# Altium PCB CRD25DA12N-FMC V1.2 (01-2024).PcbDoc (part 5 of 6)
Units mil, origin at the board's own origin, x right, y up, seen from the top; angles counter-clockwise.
Board outline 8000 x 8000 mil, 6 copper layers (Top Layer, Layer 2, Layer 3, Layer 4, Layer 5, Bottom Layer), stack 91 mil thick; 574 components, 325 nets, 1631 pads, 633 vias.
Unrouted connection lines stored in the file: 1.
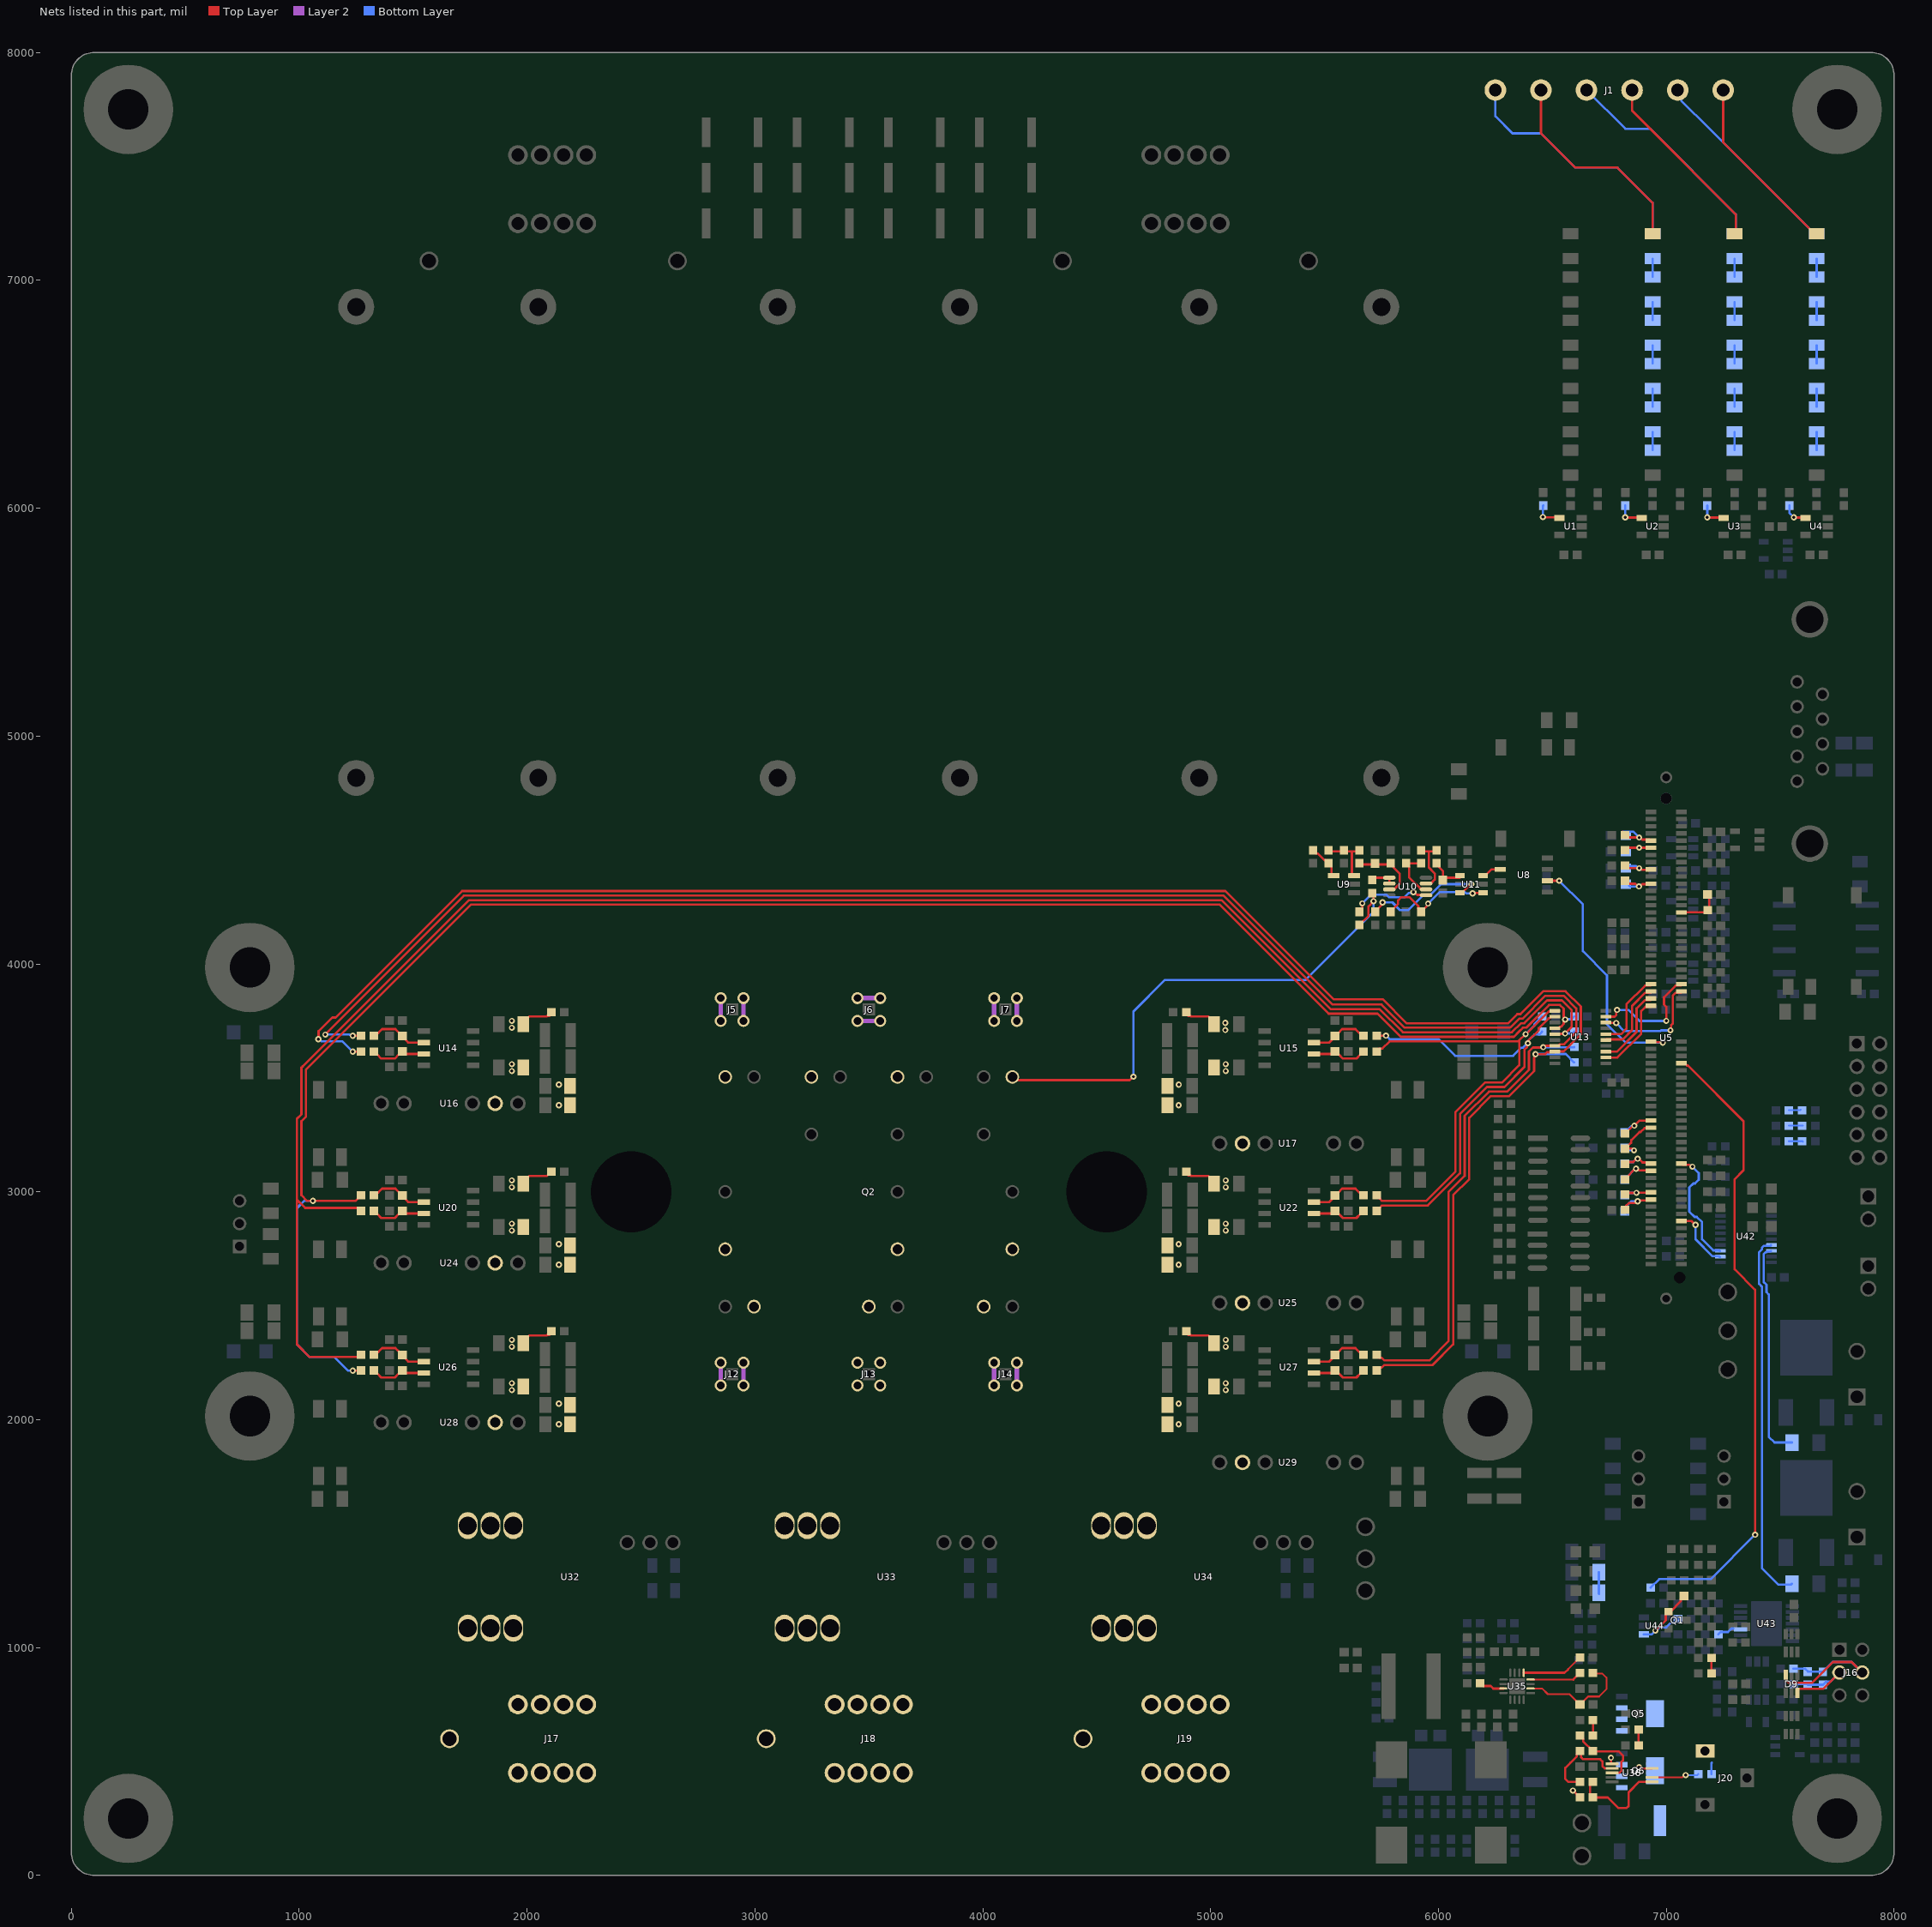
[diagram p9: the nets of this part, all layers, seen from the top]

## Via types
v1: diameter 27, hole 13, Top Layer to Bottom Layer, tented both sides, 537 vias
v2: diameter 50, hole 28, Top Layer to Bottom Layer, tented both sides, 76 vias
v3: diameter 19.68, hole 7.87, Top Layer to Bottom Layer, tented top, 15 vias
v4: diameter 19.68, hole 7.87, Top Layer to Bottom Layer, tented both sides, 5 vias

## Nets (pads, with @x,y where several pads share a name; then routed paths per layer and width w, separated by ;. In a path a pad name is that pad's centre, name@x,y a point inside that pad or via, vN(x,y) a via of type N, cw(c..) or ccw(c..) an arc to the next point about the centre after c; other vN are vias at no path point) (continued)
NetR137_2: R137.2 U35.5 | length 274.5
  Top Layer w8: 6569.74,905.26 6620.47,956 R137.2@6621.38,956
  Top Layer w10: U35.5@6374.53,889.23 6553.71,889.23 6569.74,905.26
NetR138_1: R138.1 R140.2 | length 68
  Top Layer w10: R140.2@7198.62,886 R138.1@7198.62,954
NetR139_1: R139.1 U35.4 | length 228.9
  Top Layer w8: U35.4@6404.23,859.53 6592,859.53
  Top Layer w10: 6592,859.53 6620.47,888 R139.1@6621.38,888
NetR141_2: R141.2 U35.11 | length 112.3
  Top Layer w10: R141.2@6183.62,844 6196.58,831.04 6229.48,831.04 6240.69,819.84 6264.04,819.84 6285.48,819.87 U35.11@6285.77,820.16
NetR142_2: R142.2 R144.1 | length 72.5
  Top Layer w10: R142.2@6675,685 6678.62,681.38 R144.1@6678.62,614
NetR143_2: R143.2 R145.1 | length 70
  Top Layer w10: R145.1@6878.62,570 R143.2@6878.62,640
NetR144_2: R144.2 R146.1 U36.3 | length 348.4
  Top Layer w8: U36.3@6761.17,449.69 6795,449.69
  Top Layer w10: R144.2@6621.38,614 6622.28,614 6635.24,601.04 6635.24,588.48 6677.72,546 R146.1@6678.62,546 6679.94,544.68 6769.2,544.68 6770.38,543.5 6791.81,543.5 6810,525.31 6810,505 6803.1,498.1 6803.1,458.1 6795,450 6795,449.69
NetR146_2: R146.2 R147.1 U36.2 | length 418.9
  Top Layer w8: 6730,469.69 U36.2@6762.91,469.69
  Top Layer w10: R147.1@6621.38,410 6570,410 6556.5,423.5 6556.5,471.5 6580,495 6607.52,522.52 6607.52,533.04 R146.2@6620.47,546 ; R146.2@6621.38,546 R146.2@6620.47,546 ; 6730,469.69 6720,479.69 6720,500 6710,510 6635,510 6626.1,518.9 6626.1,536.38 6626.1,540.38 R146.2@6620.47,546
NetR147_2: R147.2 R148.1 U36.6 | length 442.1
  Top Layer w10: R148.1@6678.62,342 6743,342 6790,295 6825.31,295 6835,304.69 6835,365 6880.63,410.63 U36.6@6937.09,410.63 ; R147.2@6678.62,410 6677.96,410 6665,397.04 6665,354.96 6677.96,342 R148.1@6679.53,342
NetR149_2: R149.2 R153.1 | length 79.8
  Bottom Layer w10: R153.1@7660,7015.12 R149.2@7660,7094.88
NetR150_2: R150.2 R154.1 | length 79.8
  Bottom Layer w10: R154.1@7300,7015.12 R150.2@7300,7094.88
NetR151_2: R151.2 R155.1 | length 79.8
  Bottom Layer w10: R155.1@6940,7015.12 R151.2@6940,7094.88
NetR153_2: R153.2 R157.1 | length 79.8
  Bottom Layer w10: R157.1@7660,6825.12 R153.2@7660,6904.88
NetR154_2: R154.2 R158.1 | length 79.8
  Bottom Layer w10: R158.1@7300,6825.12 R154.2@7300,6904.88
NetR155_2: R155.2 R159.1 | length 79.8
  Bottom Layer w10: R159.1@6940,6825.12 R155.2@6940,6904.88
NetR157_2: R157.2 R161.1 | length 79.8
  Bottom Layer w10: R161.1@7660,6635.12 R157.2@7660,6714.88
NetR158_2: R158.2 R162.1 | length 79.8
  Bottom Layer w10: R162.1@7300,6635.12 R158.2@7300,6714.88
NetR159_2: R159.2 R163.1 | length 79.8
  Bottom Layer w10: R163.1@6940,6635.12 R159.2@6940,6714.88
NetR161_2: R161.2 R165.1 | length 79.8
  Bottom Layer w10: R165.1@7660,6445.12 R161.2@7660,6524.88
NetR162_2: R162.2 R166.1 | length 79.8
  Bottom Layer w10: R166.1@7300,6445.12 R162.2@7300,6524.88
NetR163_2: R163.2 R167.1 | length 79.8
  Bottom Layer w10: R167.1@6940,6445.12 R163.2@6940,6524.88
NetR165_2: R165.2 R169.1 | length 79.8
  Bottom Layer w10: R169.1@7660,6255.12 R165.2@7660,6334.88
NetR166_2: R166.2 R170.1 | length 79.8
  Bottom Layer w10: R170.1@7300,6255.12 R166.2@7300,6334.88
NetR167_2: R167.2 R171.1 | length 79.8
  Bottom Layer w10: R171.1@6940,6255.12 R167.2@6940,6334.88
NetR174_2: R174.2 U4.4 | length 112.5
  Top Layer w10: v1(7560,5960) 7561.3,5958.7 7610.47,5958.7 U4.4@7611.77,5957.4
  Bottom Layer w10: R174.2@7540,6011.38 7540,5980 v1(7560,5960)
NetR176_2: R176.2 U3.4 | length 124.2
  Top Layer w10: v1(7180,5960) 7181.3,5958.7 7250.47,5958.7 U3.4@7251.77,5957.4
  Bottom Layer w10: v1(7180,5960) R176.2@7180,6011.38
NetR178_2: R178.2 U2.4 | length 124.2
  Top Layer w10: v1(6820,5960) 6821.3,5958.7 6890.47,5958.7 U2.4@6891.77,5957.4
  Bottom Layer w10: v1(6820,5960) R178.2@6820,6011.38
NetR180_2: R180.2 U1.4 | length 125.4
  Top Layer w10: v1(6458.58,5961.42) 6460.59,5959.41 6529.76,5959.41 U1.4@6531.77,5957.4
  Bottom Layer w10: v1(6458.58,5961.42) 6458.58,6009.96 R180.2@6460,6011.38
NetR204_2: R204.2 R205.1 | length 52.2
  Bottom Layer w8: R205.1@7538.62,3358 7588,3358 R204.2@7590,3360
NetR206_2: R206.2 R207.1 | length 61.4
  Bottom Layer w8: R207.1@7538.62,3290 R206.2@7596.38,3290 R206.2@7600,3290
NetR208_2: R208.2 R209.1 | length 62.2
  Bottom Layer w8: R209.1@7538.62,3222 R208.2@7596.38,3222 7598,3222 R208.2@7600,3220
NetR216_1: R216.1 R219.2 | length 95.4
  Bottom Layer w10: R216.1@6704.1,1330 R219.2@6704.1,1240 6704.1,1235.9 R219.2@6705,1235
NetR228_1: R228.1 U43.3 | length 76.6
  Bottom Layer w10: R228.1@7228.62,1058 7238.6,1067.98 7271.26,1067.98 7286.55,1083.27 7294.76,1083.27
NetR246_1: R246.1 U36.7 | length 210.4
  Top Layer w8: U36.7@6937.09,430.32 7070.17,430.32 7079.86,440 v1(7085,440)
  Bottom Layer w8: v1(7085,440) 7136.38,440 R246.1@7141.38,445
NTC1: Q2.NTC2 R56.1 R59.2 | length 2278.5
  Top Layer w10: Q2.NTC2@4129.92,3503.94 4143.45,3503.94 4157.39,3490 4645.4,3490 4660.4,3505 v1(4661.5,3505) ; R59.2@5654,4171.38 5654,4172.28 5693.04,4211.33 5693.04,4253.04 v1(5715,4275) 5715,4306.38 R56.1@5710,4311.38
  Bottom Layer w10: v1(4661.5,3505) 4661.5,3791.5 4800,3930 5416.72,3930 5715,4228.28 v1(5715,4275)
NTC1_BUF: R59.1 U10.5 | length 359
  Top Layer w10: R59.1@5654,4228.62 ccw(c5654,4240.37) 5665.75,4240.37 v1(5665.75,4265.68) ; v1(5890.31,4315.31) 5894.3,4315.31 5906.51,4303.09 5944.23,4303.09 U10.5@5945.71,4301.61
  Bottom Layer w10: v1(5665.75,4265.68) 5665.75,4266.05 5703.19,4303.5 5772.11,4303.5 5782.79,4292.81 5851.71,4292.81 5870.94,4312.05 5887.05,4312.05 v1(5890.31,4315.31)
NTC1_FB: R53.2 R54.2 U10.7 | length 246.9
  Top Layer w10: R53.2@5925,4493.62 5958.5,4493.62 ; U10.7@5945.71,4352.8 5966.5,4352.8 5972.23,4358.53 5972.64,4358.53 5984.27,4370.16 5984.27,4396.74 5958.5,4422.51 5958.5,4493.62 ; R54.2@5992,4493.62 5958.5,4493.62
NTC1_INV: R52.2 R53.1 U10.6 | length 229.9
  Top Layer w10: R53.1@5925,4441.38 R52.2@5858,4441.38 5870.96,4428.42 5870.96,4380.76 5918.78,4332.94 5919.19,4332.94 5924.92,4327.2 U10.6@5945.71,4327.2
NTC_B0: R47.2 R48.1 R49.2 U9.3 | length 251.4
  Top Layer w10: R47.2@5515,4493.62 5586,4493.62 5620,4493.62 ; U9.3@5630.08,4387.4 5626.61,4387.4 5620,4394.02 5620,4437.94 5620,4493.62 ; R49.2@5654,4493.62 5620,4493.62
NTC_B1: R46.2 R47.1 U9.4 | length 155.8
  Top Layer w10: R46.2@5450,4498.62 5450,4497.72 5462.96,4484.76 5470.52,4484.76 5500.04,4455.24 5505.04,4455.24 5518,4442.28 R47.1@5518,4441.38 5518,4437.28 5530.96,4424.33 5530.96,4396.37 U9.4@5539.92,4387.4
NTC_BIAS: C14.1 R49.1 R51.2 U10.3 | length 295.5
  Top Layer w10: R49.1@5654,4436.38 5721.96,4436.38 5722,4436.42 5794.05,4436.42 5802.96,4427.52 5802.96,4423.42 5830,4396.38 5830,4351.72 5811.22,4332.94 5810.81,4332.94 5805.08,4327.2 U10.3@5784.29,4327.2
NTC_BIAS_BUF: R56.2 U10.1 U10.2 | length 103.9
  Top Layer w10: R56.2@5710,4368.62 5719.76,4378.39 U10.1@5784.29,4378.39 U10.2@5784.29,4352.8
NTC_DIV: R61.2 R62.1 U11.4 | length 523.1
  Top Layer w10: R61.2@5790,4228.62 5790,4229.53 5823.08,4262.6 5823.08,4278.38 5837.51,4292.81 5851.71,4292.81 5852,4293.11 5872.2,4293.11 5912.04,4253.26 5912.04,4241.58 R62.1@5925,4228.62 ; R62.1@5925,4225 R62.1@5925,4228.62 ; v1(5955,4265) 5951.75,4261.75 5951.75,4256.27 5925,4229.53 R62.1@5925,4228.62 ; v1(6150.15,4309.85) 6151.53,4311.22 6193.62,4311.22 U11.4@6196.2,4313.8
  Bottom Layer w10: v1(5955,4265) 6005,4315 6116.65,4315 6121.65,4310 6150,4310 v1(6150.15,4309.85)
NTC_ISO: U5.57 U8.6 | length 1100.5
  Top Layer w10: U8.6@6478.35,4365 v1(6530,4365) ; U5.57@6933.07,3659.25 6935.2,3657.13 6982.87,3657.13 v1(6985,3655)
  Bottom Layer w10: v1(6530,4365) 6634.13,4260.87 6634.13,4055.87 6740,3950 6740,3735 6820,3655 v1(6985,3655)
NTC_MOD: C18.1 R54.1 U11.1 | length 142.2
  Top Layer w10: R54.1@5992,4436.38 5992,4435.47 6020,4407.47 6020,4380.52 6023.12,4377.4 6024.22,4378.5 U11.1@6093.01,4378.5
NTC_PWM: U8.2 U11.6 | length 90.3
  Top Layer w10: U11.6@6196.18,4387.4 6206.02,4387.4 6233.62,4415 U8.2@6271.65,4415 U8.2@6275,4415
NTC_SET: R60.2 U11.3 | length 565.9
  Top Layer w10: R60.2@5722,4228.62 5722,4229.53 v1@5751.75,4259.27 ; U11.3@6093.82,4312.6 6103.66,4312.6 6141.06,4350 v1(6145,4350) v1@6150,4350
  Bottom Layer w10: v1(5755,4270) 5798.05,4270 5831.94,4236.11 5867.58,4236.11 5931.12,4299.64 5961.36,4299.64 6011.72,4350 v1(6145,4350)
RELAY1: R217.1 U42.17 | length 1624.2
  Bottom Layer w10: U42.17@7459.41,2765.59 7456.69,2762.87 7428.03,2762.87 7420,2754.84 7420,2747.41 7407.58,2734.99 7407.58,2596.32 7420,2583.91 7420,1348.28 7492.43,1275.86 7547.65,1275.86 R217.1@7551.79,1280
RELAY1_OUT: U5.92 U42.3 | length 532.2
  Top Layer w10: U5.92@7066.93,3123.82 7071.77,3118.98 7101.42,3118.98 7110.4,3110 v1(7115,3110)
  Bottom Layer w10: v1(7115,3110) 7142.55,3082.45 7142.55,3052.99 7126.32,3036.75 7119.15,3036.75 7101.5,3019.11 7101.5,2913.19 7124.77,2889.92 7133.73,2889.92 7157,2866.65 7157,2792.03 7206.16,2742.87 7232.13,2742.87 U42.3@7235,2740
RELAY2: R214.1 U42.18 | length 960.6
  Bottom Layer w10: U42.18@7459.41,2740 7457.56,2738.15 7443.58,2738.15 7439.74,2734.31 7435.18,2734.31 7427.58,2726.71 7427.58,2604.61 7440,2592.19 7440,2560 7450,2550 7450,1925 7475,1900 7551.56,1900 R214.1@7551.79,1899.76
RELAY2_OUT: U5.108 U42.2 | length 268.3
  Top Layer w10: U5.108@7066.93,2871.85 7109.87,2871.85 v1@7126.87,2854.85
  Bottom Layer w10: v1(7128.5,2854.85) 7128.5,2792.25 7203.47,2717.28 7232.13,2717.28 U42.2@7235,2714.41
RSLV_PWM: R218.1 U5.64 | length 2800.8
  Top Layer w10: U5.64@7066.93,3564.76 7080.71,3564.76 7091.36,3554.11 7095.11,3554.11 7101.55,3547.67 7338.86,3310.36 7338.86,3093.86 7300,3055 7300,2660 7390,2570 v1(7390,1495)
  Bottom Layer w10: R218.1@6931.38,1263 6932.28,1263 6969.17,1299.89 7194.89,1299.89 v1(7390,1495)
RSLV_PWM_FILT: C95.1 Q1.1 R224.2 U44.1 | length 383.9
  Top Layer w10: v1(6952.26,1074.16) 6997.91,1119.81 6997.91,1146.65 7008.66,1157.4 Q1.1@7010.63,1157.4 ; Q1.1@7015.63,1157.4 7017.6,1157.4 7063.76,1203.57 7063.76,1213.14 7077.63,1227 C95.1@7078.58,1227
  Bottom Layer w10: U44.1@6901.77,1057.6 6935.7,1057.6 v1(6952.26,1074.16) 6956.86,1074.16 6970.8,1088.1 7000.44,1088.1 7019.3,1106.96 7031.43,1106.96 7050.47,1126 R224.2@7051.38,1126
S1: C52.1 C62.2 C67.1 C71.2 J5.2 J5.3 J5.4 J5.5 Q2.S1 R88.1 U24.6 | length 346.1
  Top Layer w10: C52.1@1984.19,3035 1984.19,3043.91 2010.28,3070 2087.47,3070 2097.47,3080 R88.1@2106.38,3080
  Layer 2 w20: J5.4@2850,3750 J5.2@2850,3850 ; J5.5@2950,3750 J5.3@2950,3850
  other v1: 2140,2680 2140,2770 1933.37,2830 1933.37,2860 1933.37,3020 1933.37,3050
S2: C77.1 C83.2 C87.1 C89.2 J12.2 J12.3 J12.4 J12.5 Q2.S2 R112.1 U28.6 | length 346.1
  Top Layer w10: C77.1@1984.19,2335 1984.19,2343.91 2010.28,2370 2086.66,2370 2088.7,2372.04 2098.42,2372.04 R112.1@2106.38,2380
  Layer 2 w20: J12.4@2850,2150 J12.2@2850,2250 ; J12.5@2950,2150 J12.3@2950,2250
  other v1: 2140,1980 2140,2070 1933.37,2130 1933.37,2160 1933.37,2320 1933.37,2350
S3: C30.1 C36.2 C40.1 C42.2 J6.2 J6.3 J6.4 J6.5 Q2.S3 R67.1 U16.6 | length 346.1
  Top Layer w10: C30.1@1984.19,3735 1984.19,3743.91 2010.28,3770 2086.66,3770 2088.7,3772.04 2098.42,3772.04 R67.1@2106.38,3780
  Layer 2 w20: J6.4@3450,3750 J6.5@3550,3750 ; J6.2@3450,3850 J6.3@3550,3850
  other v1: 2140,3380 2140,3470 1933.37,3530 1933.37,3560 1933.37,3720 1933.37,3750
S4: C78.2 C84.1 C88.1 C90.2 J13.2 J13.3 J13.4 J13.5 Q2.S4 R113.1 U29.6 | length 146.1
  Top Layer w10: R113.1@4893.62,2380 4901.58,2372.04 4911.3,2372.04 4913.34,2370 4989.72,2370 5015.81,2343.91 C78.2@5015.81,2335
  other v1: 4860,1980 4860,2070 5066.63,2130 5066.63,2160 5066.63,2320 5066.63,2350
S5: C31.2 C37.1 C41.1 C43.2 J7.2 J7.3 J7.4 J7.5 Q2.S5 R68.1 U17.6 | length 346.1
  Top Layer w10: R68.1@4893.62,3780 4901.58,3772.04 4911.3,3772.04 4913.34,3770 4989.72,3770 5015.81,3743.91 C31.2@5015.81,3735
  Layer 2 w20: J7.4@4050,3750 J7.2@4050,3850 ; J7.5@4150,3750 J7.3@4150,3850
  other v1: 4860,3380 4860.39,3469.95 5066.63,3530 5066.63,3560 5065,3710 5065,3741.5
S6: C53.2 C63.1 C68.1 C72.2 J14.2 J14.3 J14.4 J14.5 Q2.S6 R89.1 U25.6 | length 346.1
  Top Layer w10: R89.1@4893.62,3080 4901.58,3072.04 4911.3,3072.04 4913.34,3070 4989.72,3070 5015.81,3043.91 C53.2@5015.81,3035
  Layer 2 w20: J14.4@4050,2150 J14.2@4050,2250 ; J14.5@4150,2150 J14.3@4150,2250
  other v1: 4860,2680 4860,2770 5066.63,2830 5066.63,2860 5066.63,3020 5066.63,3050
SIN: C19.1 R58.2 U5.30 | length 184.6
  Top Layer w10: U5.30@7066.93,4226.18 7171.56,4226.18 R58.2@7181.38,4236 ; R58.2@7187.44,4240 7188.72,4241.28 7188.72,4303.72 C19.1@7190,4305
SIN_N: C177.2 D9.6 J16.4 R235.1 R236.1 | length 767.9
  Top Layer w10: D9.6@7524.41,879.37 7528.27,875.51 7528.27,854.05 7536.59,845.73 7640.73,845.73 7731.5,936.5 7813.5,936.5 J16.4@7860,890
  Bottom Layer w10: R235.1@7558.62,907 7609.53,907 C177.2@7622,894.53 ; C177.2@7622,893.58 7689.96,893.58 R236.1@7689.96,896.48 ; R236.1@7688,893.62 7688,894.53 R236.1@7689.96,896.48 ; J16.4@7860,890 7813.5,936.5 7729.97,936.5 R236.1@7689.96,896.48
SIN_P: C177.1 D9.3 J16.3 R236.2 R238.1 | length 454.7
  Top Layer w10: D9.3@7575.59,800.63 7575.59,814.41 7579.45,818.27 7688.27,818.27 J16.3@7760,890
  Bottom Layer w10: R238.1@7558.62,839 7619.42,839 7622,836.42 R236.2@7688,836.38 7688,837.28 7700.96,850.24 7720.24,850.24 J16.3@7760,890
U: Q2.U U32.4 U32.5 U32.6
U_HI_OC: C145.1 R84.2 U5.79 | length 191.4
  Top Layer w10: R84.2@6818.62,3256 6819.53,3256 6850.27,3286.75 6856.75,3286.75 6882.8,3312.8 U5.79@6933.07,3312.8
  Bottom Layer w10: C145.1@6818.58,3261 6819.53,3261 6845.27,3286.75 6856.75,3286.75 v1(6860,3290)
U_HS: R94.1 R121.1 R197.2 U13.14 | length 8144.5
  Top Layer w10: v1(1235,2215) 1270.38,2215 R121.1@1271.38,2216 ; R94.1@1271.38,2984 1270.47,2984 1257.52,2971.04 1257.52,2970.14 1247.38,2960 v1(1060,2960) 1035,2960 1010,2985 1010,3310 1030,3330 1030,3536.41 1753.59,4260 5040.15,4260 5518.28,3781.86 5733.28,3781.86 5835.15,3680 6331.11,3680 6355.11,3704 6371.11,3720 6385.17,3720 6485.17,3820 6533.43,3820 6550,3803.43 v1@6550,3755 ; U13.14@6510.59,3717.36 6526.34,3717.36 6533.06,3724.08 6537.62,3724.08 6550,3736.46 v1@6550,3755 ; v1(6556.77,3755.76) 6550.76,3755.76 v1@6550,3755
  Bottom Layer w10: v1(1060,2960) 1021.65,2960 990,2928.35 990,2330 1045,2275 1155,2275 1215,2215 v1(1235,2215) ; v1(6556.77,3755.76) 6558.05,3757.04 6583.42,3757.04 R197.2@6596.38,3770
U_HS+_FILT: C56.1 R94.2 U20.2 | length 256.7
  Top Layer w10: R94.2@1328.62,2984 1341.58,2996.96 1346.96,2996.96 1363.86,3013.86 1422.76,3013.86 1438.76,2997.86 1449.53,2987.1 1449.53,2984 1478.53,2955 U20.2@1546.73,2955
U_HS-_FILT: C81.1 R121.2 U26.3 | length 258
  Top Layer w10: R121.2@1328.62,2216 1329.53,2216 1342.48,2203.04 1342.48,2202.52 1360,2185 1420,2185 1437.14,2202.14 1447.14,2202.14 1453.58,2208.58 C81.1@1453.58,2216 ; C81.1@1448.58,2216 1454.79,2209.79 1459.58,2205 U26.3@1546.73,2205
U_HS_PWM: U5.49 U13.6 | length 353.2
  Top Layer w10: U13.6@6735,3691.77 6801.77,3691.77 6825,3715 6825,3822.63 6906.98,3904.61 6930.16,3904.61 U5.49@6935,3909.45
U_LO_OC: C146.1 R85.2 U5.81 | length 250
  Top Layer w10: v1@6855,3189.96 6858.45,3186.51 v1(6858.45,3181.91) ; v1@6855,3190 R85.2@6820.53,3190 ; U5.81@6933.07,3281.3 6931.77,3280 6905,3280 6887.5,3262.5 6882.19,3262.5 6846.5,3226.81 6846.5,3215 6845.53,3215 R85.2@6820.53,3190 ; R85.2@6820.53,3190 6819.62,3190 R85.2@6818.62,3189 6819.53,3189 R85.2@6820.53,3190
  Bottom Layer w10: C146.1@6818.58,3192 6828.67,3181.91 v1(6858.45,3181.91)
U_LS: R98.1 R118.1 R199.2 U13.15 | length 8232.8
  Top Layer w10: 1015,3550 1010,3545 1010,3340 990,3320 990,2965 ; 1015.15,3549.85 1745.31,4280 5048.43,4280 5526.57,3801.86 5741.57,3801.86 5843.43,3700 6322.82,3700 6362.82,3740 6376.89,3740 6476.89,3840 6541.72,3840 6585.27,3796.45 6585.27,3724.28 6554.37,3693.39 6512.2,3693.39 U13.15@6510.59,3691.77 ; R118.1@1271.38,2284 1262.38,2275 1045,2275 990,2330 990,2965 ; R98.1@1271.38,2916 1258.42,2928.96 1026.04,2928.96 990,2965
  Bottom Layer w10: v1(6555.98,3695) 6588.38,3695 R199.2@6596.38,3703
U_LS+_FILT: C79.1 R118.2 U26.2 | length 256.7
  Top Layer w10: R118.2@1328.62,2284 1341.58,2296.96 1346.96,2296.96 1363.86,2313.86 1422.76,2313.86 1438.76,2297.86 1449.53,2287.1 1449.53,2284 1478.53,2255 U26.2@1546.73,2255
U_LS-_FILT: C59.1 R98.2 U20.3 | length 258
  Top Layer w10: R98.2@1328.62,2916 1329.53,2916 1342.48,2903.04 1342.48,2902.52 1360,2885 1420,2885 1437.14,2902.14 1447.14,2902.14 1453.58,2908.58 C59.1@1453.58,2916 ; C59.1@1448.58,2916 1454.79,2909.79 1459.58,2905 U20.3@1546.73,2905
U_LS_PWM: U5.51 U13.5 | length 349.9
  Top Layer w10: U13.5@6735,3666.18 6737.72,3668.9 6808.84,3668.9 6850,3710.05 6850,3816.13 6906.98,3873.11 6930.16,3873.11 U5.51@6935,3877.95
U_OUT: J17.1 J17.2 J17.3 J17.4 J17.5 J17.6 J17.7 J17.8 TP11.1 U32.1 U32.2 U32.3
V: Q2.V U33.4 U33.5 U33.6
V_HI_OC: C148.1 R86.2 U5.91 | length 197.9
  Top Layer w10: R86.2@6822.09,3115 6822.09,3117.95 6834.8,3130.67 6855.15,3130.67 6869.65,3145.16 v1(6874.25,3145.16) 6878.85,3145.16 6895.35,3128.66 6928.23,3128.66 U5.91@6933.07,3123.82
  Bottom Layer w10: C148.1@6822.09,3116.97 6835.79,3130.67 6855.15,3130.67 6869.65,3145.16 v1(6874.25,3145.16)
V_HS: R71.1 R119.1 R201.2 U13.17 | length 8533.3
  Top Layer w10: v1(1115,3690) 1115,3691.72 1723.28,4300 5056.72,4300 5534.85,3821.86 5749.85,3821.86 5851.72,3720 6314.54,3720 6354.54,3760 6368.6,3760 6468.6,3860 6550,3860 6605.27,3804.73 6605.27,3700.27 6552.31,3647.31 6533.06,3647.31 6526.34,3640.59 U13.17@6510.59,3640.59 6470.19,3640.59 6464.6,3635 v1@6460,3635 ; v1(1235,3685) 1270.38,3685 R71.1@1271.38,3684 ; R119.1@5728.62,2284 5741.58,2271.04 5751.58,2271.04 5762.62,2260 5960,2260 6045,2345 6045,3000 6115,3070 6115,3333.43 6221.57,3440 6301.72,3440 6397.35,3535.64 6397.35,3615.78 6414.9,3633.33 6458.6,3633.33 v1(6459.74,3634.47)
  Bottom Layer w10: v1(1115,3690) 1220.64,3690 1222.39,3688.25 1231.75,3688.25 v1(1235,3685) ; v1(6459.74,3634.47) 6594.85,3634.47 R201.2@6596.38,3636
V_HS+_FILT: C32.1 R71.2 U14.2 | length 256.7
  Top Layer w10: R71.2@1328.62,3684 1341.58,3696.96 1346.96,3696.96 1363.86,3713.86 1422.76,3713.86 1438.76,3697.86 1449.53,3687.1 1449.53,3684 1478.53,3655 U14.2@1546.73,3655
V_HS-_FILT: C80.1 R119.2 U27.3 | length 256.7
  Top Layer w10: U27.3@5453.27,2255 5521.47,2255 5550.47,2284 5550.47,2287.1 5561.24,2297.86 5577.24,2313.86 5636.14,2313.86 5653.04,2296.96 5658.42,2296.96 R119.2@5671.38,2284
V_HS_PWM: U5.53 U13.3 | length 356.1
  Top Layer w10: U13.3@6735,3615 6783.23,3615 6870,3701.77 6870,3804.64 6906.98,3841.61 6930.16,3841.61 U5.53@6935,3846.46
V_LO_OC: C149.1 R90.2 U5.93 | length 204.7
  Top Layer w10: R90.2@6820,3055 6820,3057.95 6863.81,3101.76 v1(6867.48,3101.76) 6872.08,3101.76 6880.33,3093.5 6931.89,3093.5 U5.93@6933.07,3092.32
  Bottom Layer w10: C149.1@6833.7,3057.16 6827.37,3063.48 6826.52,3063.48 6864.79,3101.76 v1(6867.48,3101.76)
V_LS: R75.1 R122.1 R202.2 U13.18 | length 8763.3
  Top Layer w10: v1(1084.21,3669.48) 1085,3670.26 1085,3705 1145,3765 1160,3765 1715,4320 5065,4320 5540,3845 5755,3845 5860,3740 6306.26,3740 6346.26,3780 6360.32,3780 6460.32,3880 6558.28,3880 6625.27,3813.02 6625.27,3691.98 6549.21,3615.93 6511.52,3615.93 6507.72,3612.13 6477.43,3612.13 6469.28,3603.98 v1@6426.71,3603.98 ; v1(1235,3615) 1270.38,3615 R75.1@1271.38,3616 ; R122.1@5728.62,2216 5741.58,2228.96 5751.58,2228.96 5762.62,2240 5975,2240 6065,2330 6065,2985 6135,3055 6135,3325.15 6229.85,3420 6310,3420 6420,3530 6420,3589.62 6422.6,3592.22 6422.6,3600.73 v1(6425.85,3603.98)
  Bottom Layer w10: v1(1084.21,3669.48) 1088.81,3669.48 1098.29,3660 1190,3660 v1(1235,3615) ; v1(6425.85,3603.98) 6426.87,3605 6558.47,3605 6595.47,3568 R202.2@6596.38,3568
V_LS+_FILT: C82.1 R122.2 U27.2 | length 258
  Top Layer w10: U27.2@5453.27,2205 5540.42,2205 5545.21,2209.79 C82.1@5551.42,2216 ; C82.1@5546.42,2216 5546.42,2208.58 5552.86,2202.14 5562.86,2202.14 5580,2185 5640,2185 5657.52,2202.52 5657.52,2203.04 5670.47,2216 R122.2@5671.38,2216
V_LS-_FILT: C34.1 R75.2 U14.3 | length 258
  Top Layer w10: R75.2@1328.62,3616 1329.53,3616 1342.48,3603.04 1342.48,3602.52 1360,3585 1420,3585 1437.14,3602.14 1447.14,3602.14 1453.58,3608.58 C34.1@1453.58,3616 ; C34.1@1448.58,3616 1454.79,3609.79 1459.58,3605 U14.3@1546.73,3605
V_LS_PWM: U5.55 U13.2 | length 351.8
  Top Layer w10: U13.2@6735,3589.41 6785.92,3589.41 6890,3693.49 6890,3793.14 6908.75,3811.89 6931.93,3811.89 U5.55@6935,3814.96
V_OUT: J18.1 J18.2 J18.3 J18.4 J18.5 J18.6 J18.7 J18.8 TP12.1 U33.1 U33.2 U33.3
VCC: C107.1 R139.2 U35.2 | length 507.9
  Top Layer w8: U35.2@6404.39,820 U35.2@6404.23,820.16 6454.84,820.16 6480,795 6575.47,795 6620.47,750 C107.1@6621.42,750 6622.37,750 6657.37,785 6705,785 6737.5,817.5 6737.5,867.5 6719.8,885.2 6681.42,885.2 R139.2@6678.62,888
VDC_MEAS: C132.1 R57.2 U5.21 | length 205.5
  Top Layer w10: R57.2@6812.09,4355 6815.04,4352.04 6863.36,4352.04 6875.4,4340 6884.6,4340 6894.45,4349.85 6934.45,4349.85 U5.21@6935,4350.39
  Bottom Layer w10: C132.1@6822.55,4365 6837.47,4350.08 6837.47,4342.89 6840.36,4340 v1(6880,4340)
VIN: J20.1 Q5.5 R148.2 R246.2 U36.1 | length 125.9
  Top Layer w10: v1(6590.28,371.98) 6590.49,371.98 6620.47,342 R148.2@6621.38,342 ; v1(6757.39,516.18) 6757.39,490.27 6758.3,489.37 U36.1@6762.91,489.37
  Bottom Layer w10: R246.2@7198.62,445 7198.62,493.62 7200,495
VIN_MID: Q5.1 Q5.2 Q5.3 Q6.1 Q6.2 Q6.3
VIN_PROTECT: Q6.5 R247.1 U36.9 | length 57.5
  Top Layer w8: v1(6880.91,474.71) 6886.06,474.71 6891.82,468.94 6915.68,468.94 6915.68,468.84 U36.9@6935.93,468.84
VU_MEAS: C124.1 R45.2 U5.9 | length 225.3
  Top Layer w10: R45.2@6808.54,4580 6808.54,4577.05 6821.26,4564.33 6824.21,4564.33 6833.54,4555 v1(6881.1,4555) 6885.7,4555 6894.72,4545.98 6928.23,4545.98 U5.9@6933.07,4541.14
  Bottom Layer w10: C124.1@6808.54,4580 6856.1,4580 v1(6881.1,4555)
VU_N: J1.2 R149.1 | length 888.5
  Bottom Layer w10: J1.2@7050,7835 7066.17,7818.83 7066.17,7788.83 7190,7665 7190.28,7665 7650.16,7205.12 R149.1@7660,7205.12
VU_P: J1.1 R16.1 | length 805.5
  Top Layer w10: J1.1@7250,7835 7250,7605.28 7650.16,7205.12 R16.1@7660,7205.12
VV_MEAS: C125.1 R50.2 U5.11 | length 204
  Top Layer w10: R50.2@6808.54,4505 6813.54,4510 v1(6881.1,4510) 6881.28,4509.82 6933.05,4509.82 U5.11@6935,4507.87
  Bottom Layer w10: C125.1@6808.54,4505 6813.54,4510 v1(6881.1,4510)
VV_N: J1.4 R150.1 | length 967.7
  Bottom Layer w10: J1.4@6650,7835 6820,7665 6930,7665 7305,7290 7305,7210.12 R150.1@7300,7205.12
VV_P: J1.3 R15.1 | length 820.4
  Top Layer w10: J1.3@6850,7835 6850,7745 7305,7290 7305,7210.12 R15.1@7300,7205.12
VW_MEAS: C127.1 R55.2 U5.17 | length 206
  Top Layer w10: R55.2@6808.54,4430 6818.54,4420 v1(6881.1,4420) 6885.7,4420 6892.32,4413.39 U5.17@6935,4413.39
  Bottom Layer w10: C127.1@6812.55,4430 6866.5,4430 6876.5,4420 v1(6881.1,4420)
VW_N: J1.6 R151.1 | length 1097.3
  Bottom Layer w10: J1.6@6250,7835 6250,7720 6325,7645 6450,7645 6600,7495 6785,7495 6940,7340 R151.1@6940,7205.12
VW_P: J1.5 R14.1 | length 941.2
  Top Layer w10: J1.5@6450,7835 6450,7645 6600,7495 6785,7495 6940,7340 R14.1@6940,7205.12
W: Q2.W U34.4 U34.5 U34.6
W_HI_OC: C152.1 R96.2 U5.99 | length 161.7
  Top Layer w10: R96.2@6823.54,2995 6823.85,2995.31 v1(6869.39,2995.31) 6870.65,2996.57 6931.81,2996.57 U5.99@6933.07,2997.83
  Bottom Layer w10: C152.1@6823.54,2995 6823.85,2995.31 v1(6869.39,2995.31) ; v1@6869.39,3000.31 v1@6874.39,3000.31
W_HS: R76.1 R95.1 R198.2 U13.11 | length 2111.1
  Top Layer w10: R95.1@5728.62,2984 5729.53,2984 5742.48,2971.04 5742.48,2970.14 5752.62,2960 5945,2960 6075,3090 6075,3350 6205,3480 6280,3480 6355,3555 6355,3660 6355,3665 ; R76.1@5728.62,3616 5741.45,3628.83 5753.83,3628.83 5785,3660 6350,3660 6355,3665 ; v1(6382.91,3691.5) v1@6381.5,3691.5 ; U13.11@6510.59,3794.13 6507.72,3791.26 6484.71,3791.26 6384.95,3691.5 v1@6381.5,3691.5 ; 6355,3665 v1@6381.5,3691.5
  Bottom Layer w10: v1(6382.91,3691.5) 6420.72,3729.3 6420.72,3735.25 6455,3769.53 R198.2@6455,3770
W_HS+_FILT: C35.1 R76.2 U15.2 | length 258
  Top Layer w10: U15.2@5453.27,3605 5540.42,3605 5545.21,3609.79 C35.1@5551.42,3616 ; C35.1@5546.42,3616 5546.42,3608.58 5552.86,3602.14 5562.86,3602.14 5580,3585 5640,3585 5657.52,3602.52 5657.52,3603.04 5670.47,3616 R76.2@5671.38,3616
W_HS-_FILT: C57.1 R95.2 U22.3 | length 256.7
  Top Layer w10: U22.3@5453.27,2955 5521.47,2955 5550.47,2984 5550.47,2987.1 5561.24,2997.86 5577.24,3013.86 5636.14,3013.86 5653.04,2996.96 5658.42,2996.96 R95.2@5671.38,2984
W_HS_PWM: U5.50 U13.9 | length 518.5
  Top Layer w10: U13.9@6735,3768.54 6773.62,3768.54 6780.61,3775.53 6780.61,3795 v1(6783.87,3798.26) ; v1(7000,3750) 7000,3811.69 6990,3821.69 6990,3853.77 7040.83,3904.61 7064.02,3904.61 U5.50@7068.86,3909.45
  Bottom Layer w10: v1(6783.87,3798.26) 6834.2,3798.26 6882.46,3750 v1(7000,3750)
W_LO_OC: C154.1 R100.2 U5.101 | length 224.3
  Top Layer w10: R100.2@6823.54,2935 6823.54,2937.95 6836.26,2950.67 6861.87,2950.67 6869.86,2958.65 v1(6874.46,2958.65) ; v1@6874.4,2960.32 6876.53,2962.44 6932.87,2962.44 U5.101@6935,2964.57
  Bottom Layer w10: C154.1@6818.58,2915 C154.1@6830,2903.58 ; C154.1@6820,2915 6820,2931.46 6823.54,2935 6823.54,2936.97 6837.24,2950.67 6839.21,2950.67 6845.9,2957.36 6873.16,2957.36 v1(6874.46,2958.65)
W_LS: R72.1 R99.1 R200.2 U13.12 | length 2163.9
  Top Layer w10: R99.1@5728.62,2916 5729.53,2916 5742.48,2928.96 5742.48,2929.86 5752.62,2940 5953.28,2940 6095,3081.72 6095,3341.72 6213.28,3460 6289.93,3460 6377.35,3547.43 6377.35,3624.07 6389.19,3635.91 6389.19,3648.62 v1(6392.44,3651.88) ; R72.1@5728.62,3684 5729.77,3685.15 v1(5769.85,3685.15) ; v1@6389.03,3655.37 v1@6392.28,3658.62 ; v1@6392.14,3660.42 6440.35,3708.63 6440.35,3718.61 6483.57,3761.83 6488.13,3761.83 6494.84,3768.54 U13.12@6510.59,3768.54
  Bottom Layer w10: v1(5769.85,3685.15) 5785,3670 5999.69,3670 6073.19,3596.5 6328.24,3596.5 6364.34,3632.6 6371.41,3632.6 6392.14,3653.33 v1@6392.14,3658.62 ; v1@6388.03,3656.29 v1(6392.44,3651.88) ; v1@6392.14,3660.42 6422.05,3690.33 6442.52,3690.33 6455,3702.81 R200.2@6455,3703
W_LS+_FILT: C60.1 R99.2 U22.2 | length 258
  Top Layer w10: U22.2@5453.27,2905 5540.42,2905 5545.21,2909.79 C60.1@5551.42,2916 ; C60.1@5546.42,2916 5546.42,2908.58 5552.86,2902.14 5562.86,2902.14 5580,2885 5640,2885 5657.52,2902.52 5657.52,2903.04 5670.47,2916 R99.2@5671.38,2916
W_LS-_FILT: C33.1 R72.2 U15.3 | length 256.7
  Top Layer w10: U15.3@5453.27,3655 5521.47,3655 5550.47,3684 5550.47,3687.1 5561.24,3697.86 5577.24,3713.86 5636.14,3713.86 5653.04,3696.96 5658.42,3696.96 R72.2@5671.38,3684
W_LS_PWM: U5.52 U13.8 | length 504.5
  Top Layer w10: U13.8@6735,3742.95 6736.2,3741.75 6779.32,3741.75 v1(6780.52,3740.55) ; v1(7018.47,3708.51) 7021.72,3711.76 7021.72,3731.42 7028.5,3738.19 7028.5,3860.78 7040.83,3873.11 7064.02,3873.11 U5.52@7068.86,3877.95
  Bottom Layer w10: v1(6780.52,3740.55) 6816.07,3705 6973.95,3705 6977.46,3708.51 v1(7018.47,3708.51)
W_OUT: J19.1 J19.2 J19.3 J19.4 J19.5 J19.6 J19.7 J19.8 TP13.1 U34.1 U34.2 U34.3
pads on no net: HS1.1 HS1.2 HS1.4 J4.1 J4.4 J4.6 J4.8 MH1.1 MH2.1 MH3.1 MH4.1 Q2.MH1 Q2.MH2 U5. U5.1 U5.2 U5.3 U5.4 U5.5 U5.6 U5.8 U5.12 U5.14 U5.15 U5.18 U5.20 U5.23 U5.24 U5.25 U5.26 U5.27 U5.28 U5.31 U5.32 U5.41 U5.42 U5.43 U5.44 U5.45 U5.54 U5.56 U5.58 U5.59 U5.60 U5.61 U5.62 U5.63 U5.66 U5.67 U5.68 U5.69 U5.70 U5.71 U5.72 U5.73 U5.75 U5.76 U5.77 U5.78 U5.80 U5.82 U5.85 U5.86 U5.89 U5.103 U5.104 U5.105 U5.107 U5.109 U5.110 U5.113 U5.114 U5.115 U5.116 U5.117 U5.118 U5.119 U5.121 U5.122 U6.8 U9.1 U9.2 U12.8 U13.13 U13.16 U35.15 U42.11 U42.12 U42.13 U42.14 U42.15 U42.16 U43.7 U43.8

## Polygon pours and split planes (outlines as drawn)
GND on Layer 2 "Layer 2-GND" (solid, pour order 1838): 95 vertices, not listed, extent 490,50 7950,6174.89
DC+ on Layer 2 "Layer 2-DC+" (solid, pour order 2308): 4265,3185 4265,3259.86 ccw(c4210,3260) 4210,3315 2805,3315.04 2805,3312.91 ccw(c2790,3260) 2735,3260 2735,3185.09 ccw(c2790,3185) 2790,3130 4209.9,3130 ccw(c4210,3185)
DC- on Layer 2 "Layer 2-DC-" (solid, pour order 2301): 2790,2880 4209.9,2880 ccw(c4210,2935) 4265,2935.46 4265,2975 ccw(c4210,2975) 4210.01,3030 2789.63,3030 ccw(c2790,2975) 2735,2975 2735,2935.06 ccw(c2790,2935)
GND_NTC on Layer 2 "Layer 2-GND_NTC 1" (solid, pour order 2105): 4004.75,3445 4649.24,3445.01 ccw(c4649.99,3479.56) 4649.99,3445 ccw(c4649.99,3479.56) 4650,3445 ccw(c4650,3480) 4685,3480 4685,3495.01 ccw(c4650,3495) 4650.25,3530 4004.88,3530 ccw(c4005,3495) 3970,3495.19 3970,3480 ccw(c4005,3480)
S5 on Layer 2 "Layer 2-S5" (solid, pour order 2092): 29 vertices, not listed, extent 3580,3174.99 5265,3860
S4 on Layer 2 "Layer 2-S4" (solid, pour order 2086): 24 vertices, not listed, extent 3425,1775 5265,2585
S3 on Layer 2 "Layer 2-S3" (solid, pour order 1912): 31 vertices, not listed, extent 1735,3330 3555,4095
S1 on Layer 2 "Layer 2-S1" (solid, pour order 1871): 27 vertices, not listed, extent 1735,2630 3075,3875
S2 on Layer 2 "Layer 2-S2" (solid, pour order 1856): 26 vertices, not listed, extent 1735,1930 3075,2585
S6 on Layer 2 "Layer 2-S6" (solid, pour order 208): 29 vertices, not listed, extent 3925,2120 5265,3110
GND_NTC on Layer 2 "Layer 2-GND_NTC" (solid, pour order 2108): 18 vertices, not listed, extent 5425,4140 6300,4995
W_OUT on Layer 2 "Layer 2-W_OUT" (solid, pour order 650): 25 vertices, not listed, extent 4325,340 5235,1620
V_OUT on Layer 2 "Layer 2-V_OUT" (solid, pour order 649): 25 vertices, not listed, extent 2935,340 3845,1620
U_OUT on Layer 2 "Layer 2-U_OUT" (solid, pour order 927): 25 vertices, not listed, extent 1545,340 2455,1620
GND_ISO on Layer 2 "Layer 2-GND_ISO" (solid, pour order 550): 7720,4445 cw(c7718.14,4368.15) 7794.99,4366.29 7795,4365.13 7795,3855 ccw(c7840.04,3855.04) 7840.09,3810 7905.12,3810 ccw(c7905.06,3854.94) 7950,3855 7950,5523.95 ccw(c7879.48,5524.36) 7879.89,5594.88 7614.1,5594.88 ccw(c7611.97,5522.91) 7540,5525.04 7540,4515.03 ccw(c7610.02,4515.02) 7610.01,4445
+15V on Layer 4 "Layer 4-+15V" (solid, pour order 2253): 66 vertices, not listed, extent 2380,50 6905,2590
+3.3V on Layer 4 "Layer 4-+3.3V" (solid, pour order 2248): 52 vertices, not listed, extent 6015,490 7950,6175
VIN on Layer 4 "Layer 4-VIN" (solid, pour order 1731): 6615,50 7245,50 ccw(c7245,120) 7315,120 7315,530 ccw(c7245,530) 7245,600 6615,600 ccw(c6615,530) 6545,530 6545,120 ccw(c6615,120)
+15V on Layer 4 "Layer 4-+15V 1" (solid, pour order 2240): 6496.49,1263.51 ccw(c6540,1275) 6528.51,1231.49
U on Layer 4 "Bottom Layer-U" (solid, pour order 2033): 25 vertices, not listed, extent 1545,1000 2955,2845
V on Layer 4 "Bottom Layer-V" (solid, pour order 2030): 17 vertices, not listed, extent 2935,1000 3710,2845.01
W on Layer 4 "Bottom Layer-W" (solid, pour order 2029): 18 vertices, not listed, extent 4045,1000 4880,2845
DC+ on Layer 4 "Layer 4-DC+" (solid, pour order 1989): 53 vertices, not listed, extent 760,3125 6240.01,7740.1
+5V_NTC on Layer 4 "Layer 2-GND_NTC" (solid, pour order 2110): 18 vertices, not listed, extent 5425,4140 6300,4995
+12V on Layer 4 "Layer 4-+12V" (solid, pour order 1686): 20 vertices, not listed, extent 490,1590 1575,3785
+5V on Layer 4 "Layer 4-+5V 1" (solid, pour order 1716): 5960,1790 ccw(c5959.91,1835.09) 6005,1835 6005,3730.21 ccw(c5960,3730) 5960,3775 5630.72,3775 5470.31,3775 ccw(c5470.23,3729.77) 5425,3730.13 5425,1835 ccw(c5470.27,1835.27) 5470.31,1790
-3V_V_HS on Layer 4 "Layer 4--3V_V_HS" (solid, pour order 1926): 1780,3330 2180.14,3330 ccw(c2180,3375) 2225,3375 2225,3765.14 ccw(c2180,3765) 2180,3810 1779.86,3810 ccw(c1780,3765) 1735,3765 1735,3374.86 ccw(c1780,3375)
-3V_W_HS on Layer 4 "Layer 4--3V_W_HS" (solid, pour order 296): 4990,3780 4940,3780 4910,3810 4814.87,3810 ccw(c4815,3765) 4770,3765 4770,3349.83 ccw(c4815,3350) 4815,3305 4890,3305 5020,3175 5220.06,3175 ccw(c5220,3220) 5265,3220 5265,3725.1 ccw(c5220,3725) 5220,3770 5000,3770
-3V_V_LS on Layer 4 "Layer 4--3V_V_LS" (solid, pour order 1928): 4990,2380 4940,2380 4910,2410 4814.87,2410 ccw(c4815,2365) 4770,2365 4770,1949.83 ccw(c4815,1950) 4815,1905 4890,1905 5020,1775 5220.06,1775 ccw(c5220,1820) 5265,1820 5265,2325.1 ccw(c5220,2325) 5220,2370 5000,2370
-3V_W_LS on Layer 4 "Layer 4--3V_W_LS" (solid, pour order 1927): 4990,3080 4940,3080 4910,3110 4814.87,3110 ccw(c4815,3065) 4770,3065 4770,2649.83 ccw(c4815,2650) 4815,2605 4890,2605 5020,2475 5220.06,2475 ccw(c5220,2520) 5265,2520 5265,3025.1 ccw(c5220,3025) 5220,3070 5000,3070
-3V_U_HS on Layer 4 "Layer 4--3V_U_HS" (solid, pour order 1864): 1780,2630 2180.14,2630 ccw(c2180,2675) 2225,2675 2225,3065.14 ccw(c2180,3065) 2180,3110 1779.86,3110 ccw(c1780,3065) 1735,3065 1735,2674.86 ccw(c1780,2675)
-3V_U_LS on Layer 4 "Layer 4--3V_U_LS" (solid, pour order 1854): 1780,1930 2180.14,1930 ccw(c2180,1975) 2225,1975 2225,2365.14 ccw(c2180,2365) 2180,2410 1779.86,2410 ccw(c1780,2365) 1735,2365 1735,1974.86 ccw(c1780,1975)
+5V_ISO on Layer 4 "Layer 4-+5V_ISO" (solid, pour order 1210): 29 vertices, not listed, extent 7540,3810 7950,5594.88
+12V on Layer 3 "Layer 3-+12V" (solid, pour order 2246): 39 vertices, not listed, extent 5425,50 7950,3935
-15V on Layer 3 "Layer 3--15V" (solid, pour order 2204): 46 vertices, not listed, extent 2380,50 6150,1515
+15V on Layer 3 "Layer 3-+15V" (solid, pour order 2179): 7845,490 ccw(c7845,595) 7950,595 7950,1185 ccw(c7905,1185) 7905,1230 6909.9,1230 ccw(c6910,1185) 6865,1185 6865,534.97 ccw(c6910,535) 6910,490
+5V on Layer 3 "Layer 3-+5V" (solid, pour order 1603): 41 vertices, not listed, extent 5975,1800 7950,6175
DC- on Layer 3 "Layer 3-DC-" (solid, pour order 1961): 57 vertices, not listed, extent 760,2878.55 6240,7740
+5V_NTC on Layer 3 "Layer 2-GND_NTC" (solid, pour order 2109): 18 vertices, not listed, extent 5425,4140 6300,4995
V_OUT on Layer 3 "Layer 3-V_OUT" (solid, pour order 653): 3845,1015 3555,1305 3555,1475.39 ccw(c3410,1475) 3410,1620 3080.47,1620 ccw(c3079.99,1475.01) 2935,1475 2935,485 ccw(c3080,485) 3080,340 3699.83,340 ccw(c3700,485) 3845,485
+5V_ALT on Layer 3 "Layer 3-+5V_ALT" (solid, pour order 1328): 20 vertices, not listed, extent 490,1590 1575,3785
+15V_W_HS on Layer 3 "Layer 3-+15V_W_HS" (solid, pour order 652): 4990,3780 4940,3780 4910,3810 4814.87,3810 ccw(c4815,3765) 4770,3765 4770,3349.83 ccw(c4815,3350) 4815,3305 4890,3305 5020,3175 5220.06,3175 ccw(c5220,3220) 5265,3220 5265,3725.1 ccw(c5220,3725) 5220,3770 5000,3770
+15V_V_LS on Layer 3 "Layer 3-+15V_V_LS" (solid, pour order 1925): 4990,2380 4940,2380 4910,2410 4814.87,2410 ccw(c4815,2365) 4770,2365 4770,1949.83 ccw(c4815,1950) 4815,1905 4890,1905 5020,1775 5220.06,1775 ccw(c5220,1820) 5265,1820 5265,2325.1 ccw(c5220,2325) 5220,2370 5000,2370
+15V_W_LS on Layer 3 "Layer 3-+15V_W_LS" (solid, pour order 1924): 4990,3080 4940,3080 4910,3110 4814.87,3110 ccw(c4815,3065) 4770,3065 4770,2649.83 ccw(c4815,2650) 4815,2605 4890,2605 5020,2475 5220.06,2475 ccw(c5220,2520) 5265,2520 5265,3025.1 ccw(c5220,3025) 5220,3070 5000,3070
W_OUT on Layer 3 "Layer 3-W_OUT" (solid, pour order 830): 5235,1015 4945,1305 4945,1475.39 ccw(c4800,1475) 4800,1620 4470.24,1620 ccw(c4470,1475) 4325,1475 4325,485 ccw(c4470,485) 4470,340 5089.83,340 ccw(c5090,485) 5235,485
U_OUT on Layer 3 "Layer 3-U_OUT" (solid, pour order 1194): 2455,1015 2165,1305 2165,1475.39 ccw(c2020,1475) 2020,1620 1690.38,1620 ccw(c1689.99,1475.01) 1545,1475 1545,485 ccw(c1690,485) 1690,340 2309.83,340 ccw(c2310,485) 2455,485
+5V_ISO on Layer 3 "Layer 3-+5V_ISO" (solid, pour order 1265): 29 vertices, not listed, extent 7540,3810 7950,5594.88
+15V_U_LS on Layer 3 "Layer 3-+15V_U_LS" (solid, pour order 1847): 1780,1930 2180.14,1930 ccw(c2180,1975) 2225,1975 2225,2365.14 ccw(c2180,2365) 2180,2410 1779.86,2410 ccw(c1780,2365) 1735,2365 1735,1974.86 ccw(c1780,1975)
+15V_U_HS on Layer 3 "Layer 3-+15V_U_HS" (solid, pour order 1855): 1780,2630 2180.14,2630 ccw(c2180,2675) 2225,2675 2225,3065.14 ccw(c2180,3065) 2180,3110 1779.86,3110 ccw(c1780,3065) 1735,3065 1735,2674.86 ccw(c1780,2675)
+15V_V_HS on Layer 3 "Layer 3-+15V_V_HS" (solid, pour order 1879): 1780,3330 2180.14,3330 ccw(c2180,3375) 2225,3375 2225,3765.14 ccw(c2180,3765) 2180,3810 1779.86,3810 ccw(c1780,3765) 1735,3765 1735,3374.86 ccw(c1780,3375)
-15V on Bottom Layer "Bottom Layer--15V" (solid, pour order 2402): 82 vertices, not listed, extent 2380,50 6680,2600
NetC189_1 on Bottom Layer "Bottom Layer-NetC187_1" (solid, pour order 2399): 6495,370 6495,425.05 ccw(c6460.02,425.02) 6460.05,460 6389.81,460 ccw(c6390,425) 6355,425 6355,410 6355,385 6443.54,385 6443.54,295 6365,295 6365,260 ccw(c6390,260) 6390,235 6460.03,235 ccw(c6459.96,270.04) 6495,270.04
+15V on Bottom Layer "Bottom Layer-+15V 3" (solid, pour order 2396): 6405,85 6405,125 6085,125 6085,84.91 ccw(c6120,85) 6120.45,50 6370.09,50 ccw(c6370,85)
GND on Bottom Layer "Bottom Layer-GND 7" (solid, pour order 2389): 5845,50 ccw(c5845,85) 5845.42,50 6035.2,50 ccw(c6035,85) 6070,85 6070,130 5810,130 5810,84.91 ccw(c5845,85)
NetC109_2 on Bottom Layer "Bottom Layer-NetC202_2" (solid, pour order 2382): 5840,500 5840,585 6070.07,585 ccw(c6070,610) 6095,610 6095,635 ccw(c6070,635) 6070,660 5850.1,660 ccw(c5850,645) 5835,645 cw(c5820,645) 5820,630 5750,630 5720,630 ccw(c5720,595) 5685,595 5685,499.85 ccw(c5720,500) 5720,465 5804.47,465 ccw(c5805,500)
NetC198_1 on Bottom Layer "Bottom Layer-NetC214_1" (solid, pour order 2369): 5685,254.88 ccw(c5720,255) 5719.87,220 5775.12,220 ccw(c5775.12,254.88) 5810,254.88 5810,295 5720,295 5720,380 5840,380 5840,419.56 ccw(c5804.67,419.67) 5804.56,455 5719.92,455 ccw(c5719.99,420.01) 5685,419.56
NetC111_2 on Bottom Layer "Bottom Layer-NetC186_2" (solid, pour order 2359): 6389.77,470 6460,470 ccw(c6460,505) 6495,505 6495,625.15 ccw(c6459.96,624.96) 6459.96,660 6360,660 6154.92,660 ccw(c6155,625) 6120,624.99 6120,599.88 ccw(c6155,600) 6155,565 6355,565 6355,504.88 ccw(c6390,505)
NetD16_2 on Bottom Layer "Bottom Layer-NetD18_2" (solid, pour order 1650): 18 vertices, not listed, extent 7470,1329.99 7950,1850
+12V on Bottom Layer "Bottom Layer-+12V 5" (solid, pour order 2340): 5825,680 5825,775 5825,1020.09 ccw(c5785,1020) 5790,1059.69 ccw(c5795,1020) 5755,1020 5755,925 5755,679.87 ccw(c5795,680) 5790,640.31 ccw(c5785,680)
GND on Bottom Layer "Bottom Layer-GND 8" (solid, pour order 2332): 5665,679.87 ccw(c5705,680) 5705,640 5705.16,640 ccw(c5705,680) 5745,680 5745,775 5745,1020.09 ccw(c5705,1020) 5705,1060 5704.84,1060 ccw(c5705,1020) 5665,1020 5665,925
VIN_MID on Bottom Layer "Bottom Layer-VIN_MID" (solid, pour order 1428): 17 vertices, not listed, extent 6715,365 6850,770
GND on Bottom Layer "NONET_L-01_P-001" (solid, pour order 2122): 6085,575 6085,310 5730,310 5730,370 5850,370 5850,575
+15V on Bottom Layer "NONET_L-01_P-001" (solid, pour order 2121): 6100,580 6100,305 6440,305 6440,375 6345,375 6345,580
GND on Bottom Layer "NONET_L-01_P-001" (solid, pour order 2126): 6405,140 6405,210 6360,210 6360,217.5 6360,295 6100,295 6100,140
VIN on Bottom Layer "Bottom Layer-VIN" (solid, pour order 1634): 18 vertices, not listed, extent 6860,485 7280,830
VIN_PROTECT on Bottom Layer "Bottom Layer-VIN_PROTECT" (solid, pour order 1442): 7055,189.81 7055,545.19 ccw(c7020,545) 7020.17,580 6879.93,580 ccw(c6880.07,559.93) 6860,559.93 6860,190 ccw(c6895,190) 6895,155 7020.25,155 ccw(c7020,190)
+12V on Bottom Layer "Bottom Layer-+12V 4" (solid, pour order 1436): 6679.88,84.82 ccw(c6714.88,85) 6715,50 6810.07,50 ccw(c6809.98,84.91) 6844.88,84.82 6844.88,295.24 ccw(c6809.99,295.11) 6810.07,330 6714.69,330 ccw(c6714.88,295.01) 6679.88,295.24
DC+ on Bottom Layer "Bottom Layer-DC+" (solid, pour order 1991): 45 vertices, not listed, extent 760,3180 6240.01,7740.1
U on Bottom Layer "Bottom Layer-U" (solid, pour order 809): 25 vertices, not listed, extent 1545,1000 2955,2845
W on Bottom Layer "Bottom Layer-W" (solid, pour order 806): 18 vertices, not listed, extent 4045,1000 4880,2845
V on Bottom Layer "Bottom Layer-V" (solid, pour order 780): 17 vertices, not listed, extent 2935,1000 3710,2845.01
+5V_ISO on Bottom Layer "+5V_ISO_L06_P517" (solid, pour order 517): 7795,4395 7795,4295 7910,4295 7910,4340 7885,4340 7885,4395
NetC92_1 on Bottom Layer "NONET_L-01_P-001" (solid, pour order 974): 5535,1865 ccw(c5535,1820) 5490,1820 5490,1730 ccw(c5535,1730) 5535,1685 5715,1685 cw(c5715,1640) 5760,1640 5760,1635 ccw(c5805,1635) 5805,1590 5925,1590 ccw(c5925,1635) 5970,1635 5970,1645.83 cw(c6004.58,1650.42) 6000,1685 ccw(c5992.08,1717.08) 6025,1720 6025,1820 ccw(c5980,1820) 5980,1865
S5 on Bottom Layer "Bottom Layer-S5" (solid, pour order 2027): 31 vertices, not listed, extent 4770,3175 5265,3810
-3V_W_HS on Bottom Layer "Bottom Layer--3V_W_HS" (solid, pour order 2026): 5210,3175 5220,3175 ccw(c5220,3220) 5265,3220 5265,3515.28 ccw(c5220,3515) 5220.06,3560 5184.85,3560 ccw(c5185,3515) 5140,3515 5140,3460.13 ccw(c5165.05,3460.05) 5165.06,3435 cw(c5165,3415) 5185,3415 5185,3200 ccw(c5210,3200)
+15V_W_HS on Bottom Layer "Bottom Layer-+15V_W_HS" (solid, pour order 2025): 5040,3175 ccw(c5039.95,3220.05) 5085,3220 5085,3230 5010,3305 5010,3370.14 ccw(c4965,3370) 4965.14,3415 ccw(c4965.15,3369.85) 4920,3370 4920,3275 5020,3175
S6 on Bottom Layer "Bottom Layer-S6" (solid, pour order 2024): 31 vertices, not listed, extent 4770,2475 5265,3110
-3V_W_LS on Bottom Layer "Bottom Layer--3V_W_LS" (solid, pour order 2023): 5210,2475 5220,2475 ccw(c5220,2520) 5265,2520 5265,2815.28 ccw(c5220,2815) 5220.06,2860 5184.85,2860 ccw(c5185,2815) 5140,2815 5140,2760.13 ccw(c5165.05,2760.05) 5165.06,2735 cw(c5165,2715) 5185,2715 5185,2500 ccw(c5210,2500)
+15V_W_LS on Bottom Layer "Bottom Layer-+15V_W_LS" (solid, pour order 2022): 5040,2475 ccw(c5039.95,2520.05) 5085,2520 5085,2530 5010,2605 5010,2670.14 ccw(c4965,2670) 4965.14,2715 ccw(c4965.15,2669.85) 4920,2670 4920,2575 5020,2475
S4 on Bottom Layer "Bottom Layer-S4" (solid, pour order 2021): 31 vertices, not listed, extent 4770,1775 5265,2410
-3V_V_LS on Bottom Layer "Bottom Layer--3V_V_LS" (solid, pour order 2003): 5210,1775 5220,1775 ccw(c5220,1820) 5265,1820 5265,2115.28 ccw(c5220,2115) 5220.06,2160 5184.85,2160 ccw(c5185,2115) 5140,2115 5140,2060.13 ccw(c5165.05,2060.05) 5165.06,2035 cw(c5165,2015) 5185,2015 5185,1800 ccw(c5210,1800)
+15V_V_LS on Bottom Layer "Bottom Layer-+15V_V_LS" (solid, pour order 1997): 5040,1775 ccw(c5039.95,1820.05) 5085,1820 5085,1830 5010,1905 5010,1970.14 ccw(c4965,1970) 4965.14,2015 ccw(c4965.15,1969.85) 4920,1970 4920,1875 5020,1775
S1 on Bottom Layer "Bottom Layer-S2" (solid, pour order 1852): 21 vertices, not listed, extent 1830,2630 2225.07,3080
-3V_U_HS on Bottom Layer "Bottom Layer--3V_U_LS" (solid, pour order 1851): 1735,2674.9 ccw(c1780,2675) 1777.5,2630.07 ccw(c1775,2675) 1820,2674.91 1820,2715.4 1820.37,2715.77 cw(c1865,2710) 1859.85,2754.7 ccw(c1859.7,2800) 1905,2799.91 1905,3035.14 ccw(c1860,3035) 1860.23,3080 1779.81,3080 ccw(c1780,3035) 1735,3035 1735,2725
+15V_U_HS on Bottom Layer "Bottom Layer-+15V_U_LS" (solid, pour order 1850): 1980,2630 2005.11,2630 ccw(c2005,2675) 2050,2674.9 2050,2680.17 ccw(c2005,2680) 2005.11,2725 1979.86,2725 ccw(c1980,2680) 1935,2680 1935,2725 1935,2677.5 1935,2674.9 ccw(c1980,2675)
-3V_U_LS on Bottom Layer "Bottom Layer--3V_U_LS" (solid, pour order 1034): 1735,1974.9 ccw(c1780,1975) 1777.5,1930.07 ccw(c1775,1975) 1820,1974.91 1820,2015.4 1820.37,2015.77 cw(c1865,2010) 1859.85,2054.7 ccw(c1859.7,2100) 1905,2099.91 1905,2335.14 ccw(c1860,2335) 1860.23,2380 1779.81,2380 ccw(c1780,2335) 1735,2335 1735,2025
GND on Bottom Layer "Bottom Layer-GND 4" (solid, pour order 1678): 6730,4275 6740.1,4275 ccw(c6740,4320) 6785,4319.97 6785,4600.16 ccw(c6740,4600) 6740.09,4645 6729.85,4645 ccw(c6730,4600) 6685,4600 6685,4319.96 ccw(c6730,4320)
GND on Bottom Layer "Bottom Layer-GND 5" (solid, pour order 1670): 7470,1979.76 ccw(c7505,1979.76) 7505.14,1944.76 7600.14,1944.76 ccw(c7600,1979.76) 7635,1979.6 7635,2119.91 ccw(c7600,2119.77) 7600.18,2154.76 7504.81,2154.76 ccw(c7505,2119.77) 7470,2119.77
+12V on Bottom Layer "Bottom Layer-+12V 2" (solid, pour order 1669): 7875,1979.54 7875,2119.85 ccw(c7840,2119.76) 7840.15,2154.76 7789.82,2154.76 ccw(c7790,2119.77) 7755,2119.88 7755,1979.76 ccw(c7790,1979.76) 7789.87,1944.76 7840.18,1944.76 ccw(c7840,1979.76)
NetD15_2 on Bottom Layer "Bottom Layer-NetD17_2" (solid, pour order 1668): 18 vertices, not listed, extent 7470,1944.76 7950,2464.76
GND on Bottom Layer "Bottom Layer-GND 6" (solid, pour order 1667): 7470,1365 ccw(c7505,1365) 7505.14,1330 7600.14,1330 ccw(c7600,1365) 7635,1364.84 7635,1505.15 ccw(c7600,1505) 7600.18,1540 7504.81,1540 ccw(c7505,1505) 7470,1505
+12V on Bottom Layer "Bottom Layer-+12V 3" (solid, pour order 1659): 7875,1364.78 7875,1505.08 ccw(c7840,1505) 7840.15,1540 7789.82,1540 ccw(c7790,1505) 7755,1505.12 7755,1365 ccw(c7790,1365) 7789.87,1330 7840.18,1330 ccw(c7840,1365)
GND on Bottom Layer "Bottom Layer-GND 9" (solid, pour order 1451): 6969.99,50 ccw(c6969.89,75.11) 6995,74.99 6995,115.03 ccw(c6969.85,114.85) 6969.95,140 6884.96,140 ccw(c6885.06,114.94) 6860,114.94 6860,74.97 ccw(c6885.11,75.11) 6885.01,50
NetC91_2 on Bottom Layer "Bottom Layer-NetC157_2" (solid, pour order 1011): 24 vertices, not listed, extent 1025,1590 1515.4,2040
+15V on Bottom Layer "Bottom Layer-+15V" (solid, pour order 1419): 5370,1334.96 5370,1489.91 ccw(c5344.91,1489.91) 5344.98,1515 5304.95,1515 ccw(c5305.07,1489.93) 5280,1489.92 5280,1405 5280,1391.3 5280,1334.98 ccw(c5305.03,1335.03) 5304.94,1310 5344.97,1310 ccw(c5344.97,1335.03)
GND on Bottom Layer "Bottom Layer-GND" (solid, pour order 1130): 5505,1234.92 5505,1365.14 ccw(c5457.49,1367.5) 5460.08,1415 5425,1415 ccw(c5425.07,1369.93) 5380,1370 5380,1234.92 ccw(c5427.46,1237.47) 5429.85,1190 5460.08,1190 ccw(c5459.99,1235.01)
+15V on Bottom Layer "Bottom Layer-+15V 1" (solid, pour order 1128): 3980,1334.96 3980,1489.91 ccw(c3954.91,1489.91) 3954.98,1515 3914.95,1515 ccw(c3915.07,1489.93) 3890,1489.92 3890,1405 3890,1391.3 3890,1334.98 ccw(c3915.03,1335.03) 3914.94,1310 3954.97,1310 ccw(c3954.97,1335.03)
GND on Bottom Layer "Bottom Layer-GND 2" (solid, pour order 1127): 4115,1234.92 4115,1365.14 ccw(c4067.49,1367.5) 4070.08,1415 4035,1415 ccw(c4035.07,1369.93) 3990,1370 3990,1234.92 ccw(c4037.46,1237.47) 4039.85,1190 4070.08,1190 ccw(c4069.99,1235.01)
+15V on Bottom Layer "Bottom Layer-+15V 2" (solid, pour order 1125): 2590,1334.96 2590,1489.91 ccw(c2564.91,1489.91) 2564.98,1515 2524.95,1515 ccw(c2525.07,1489.93) 2500,1489.92 2500,1405 2500,1391.3 2500,1334.98 ccw(c2525.03,1335.03) 2524.94,1310 2564.97,1310 ccw(c2564.97,1335.03)
GND on Bottom Layer "Bottom Layer-GND 3" (solid, pour order 1124): 2720,1234.92 2720,1365 ccw(c2674.92,1369.95) 2680.08,1415 2645,1415 ccw(c2645.07,1369.93) 2600,1370 2600,1234.92 ccw(c2647.46,1237.47) 2649.85,1190 2675.08,1190 ccw(c2674.99,1235.01)
NetC48_2 on Bottom Layer "Bottom Layer-NetC106_2" (solid, pour order 1122): 24 vertices, not listed, extent 1025,2990 1515.4,3440
NetC73_2 on Bottom Layer "Bottom Layer-NetC136_2" (solid, pour order 1108): 24 vertices, not listed, extent 1025,2290 1515.4,2740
